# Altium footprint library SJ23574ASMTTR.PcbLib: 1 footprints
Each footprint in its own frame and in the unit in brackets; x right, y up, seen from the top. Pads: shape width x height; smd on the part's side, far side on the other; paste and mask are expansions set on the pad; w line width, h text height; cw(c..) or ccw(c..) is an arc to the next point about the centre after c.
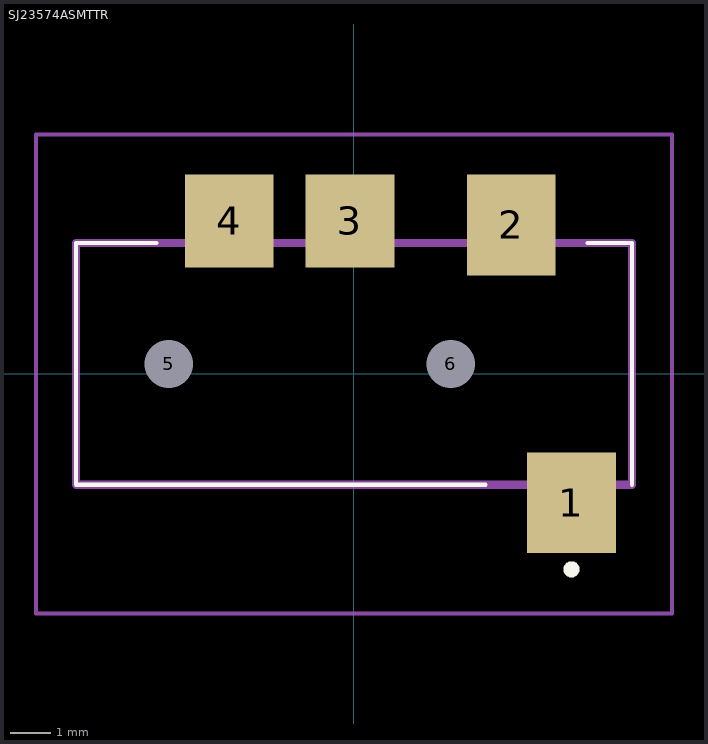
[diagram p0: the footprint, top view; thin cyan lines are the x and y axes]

## SJ23574ASMTTR [mm]
pads (6):
  rect 2.2x2.5 smd: 1(5.4,-3.2) 2(3.9,3.7)
  rect 2.2x2.3 smd: 3(-0.1,3.8) 4(-3.1,3.8)
  round 0.6 hole 1.2 unplated: 5(-4.6,0.25) 6(2.4,0.25)
Top Overlay:
  lines w0.1: -4.9,3.25 -6.9,3.25 -6.9,-2.75 3.26,-2.75 ; 5.8,3.25 6.9,3.25 6.9,-2.75
  lines w0.2: 5.3,-4.85 5.3,-4.85 ; 5.3,-4.85 cw(c5.4,-4.85) 5.5,-4.85 ; 5.3,-4.85 ccw(c5.4,-4.85) 5.5,-4.85 ; 5.5,-4.85 5.5,-4.85
Mechanical 15:
  lines w0.2: -6.9,-2.75 6.9,-2.75 6.9,3.25 -6.9,3.25 -6.9,-2.75
Mechanical 20:
  lines w0.1: -7.9,-5.95 7.9,-5.95 7.9,5.95 -7.9,5.95 -7.9,-5.95
3D body "SJ2-3574A-SMT-TR.stp": height 5.8, standoff -4.65, extent -10,-3.376 10,3.376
